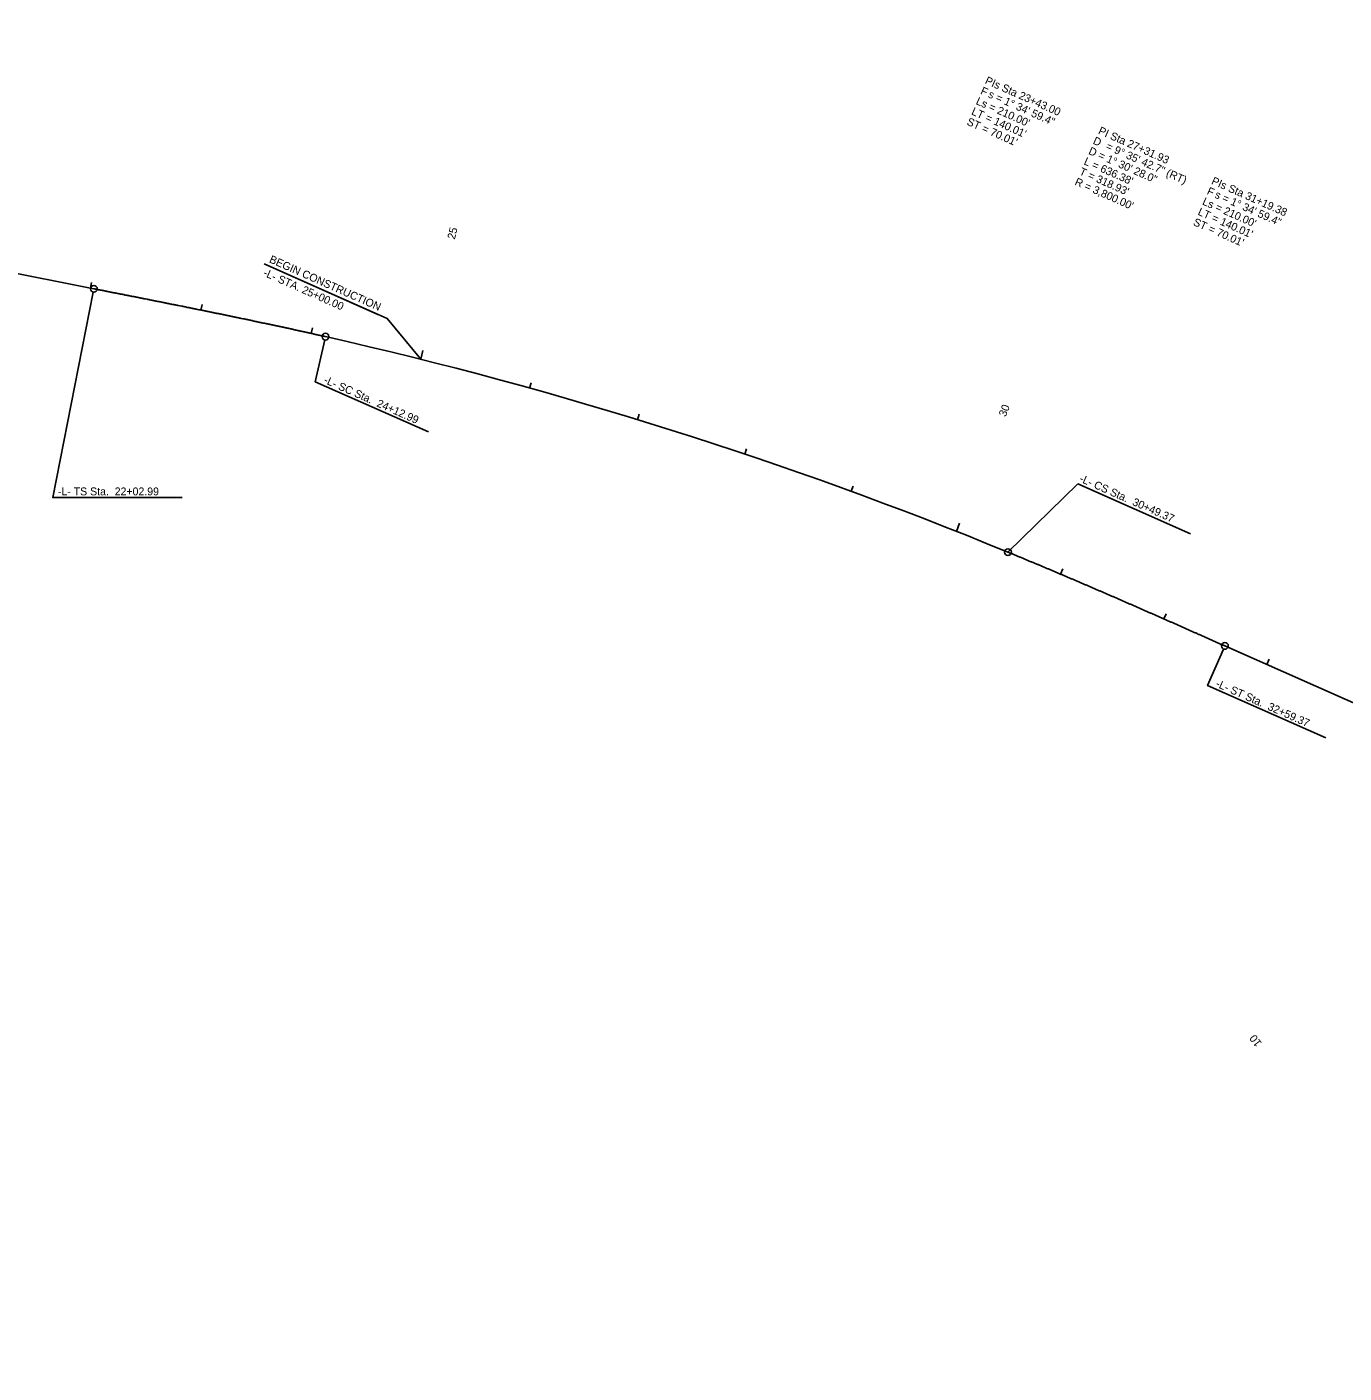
# Model space of a CAD drawing. Extents: x 1636713 to 1642783, y 841520 to 844371.
# Drawn here: x 1637837 to 1639007, y 842626 to 843822 of the extents above; entities that cross this region are included whole.
import ezdxf

# ---------------------------------------------------------------- set-up
doc = ezdxf.new("R2010")
doc.units = 0
for name, color, linetype in [('Prop Horizontal Alignment', 7, 'Continuous'), ('Prop Horizontal Alignment Curve and Spiral Data', 7, 'Continuous'), ('Prop Horizontal Alignment Station Label', 7, 'Continuous'), ('Prop Horizontal Alignment Tick Label', 7, 'Continuous'), ('Prop Horizontal Alignment Tick Large', 7, 'Continuous'), ('Prop Horizontal Alignment Tick Small', 7, 'Continuous')]:
    doc.layers.add(name, color=color, linetype=linetype)

msp = doc.modelspace()

# ---------------------------------------------------------------- linework, layer by layer
at = {"layer": 'Prop Horizontal Alignment'}
for p, q in [((1636716.1, 843822.5), (1637896.4, 843589.8)), ((1638900.9, 843272.5), (1640357.9, 842626.5))]:
    msp.add_line(p, q, dxfattribs=at)
msp.add_arc((1637264.4, 839840.8), 3800, 67.6703, 77.2655, dxfattribs=at)
for points in [[(1637896.4, 843589.8), (1637899.2, 843589.3), (1637902, 843588.7), (1637904.8, 843588.2), (1637907.5, 843587.6), (1637910.3, 843587.1), (1637913.1, 843586.5), (1637915.9, 843586), (1637918.7, 843585.4), (1637921.5, 843584.9), (1637924.2, 843584.3), (1637927, 843583.8), (1637929.8, 843583.2), (1637932.6, 843582.7), (1637935.4, 843582.1), (1637938.2, 843581.6), (1637941, 843581), (1637943.7, 843580.5), (1637946.5, 843579.9), (1637949.3, 843579.4), (1637952.1, 843578.8), (1637954.9, 843578.3), (1637957.7, 843577.7), (1637960.4, 843577.1), (1637963.2, 843576.6), (1637966, 843576), (1637968.8, 843575.5), (1637971.6, 843574.9), (1637974.3, 843574.4), (1637977.1, 843573.8), (1637979.9, 843573.2), (1637982.7, 843572.7), (1637985.5, 843572.1), (1637988.3, 843571.5), (1637991, 843571), (1637993.8, 843570.4), (1637996.6, 843569.8), (1637999.4, 843569.3), (1638002.2, 843568.7), (1638004.9, 843568.1), (1638007.7, 843567.6), (1638010.5, 843567), (1638013.3, 843566.4), (1638016.1, 843565.9), (1638018.8, 843565.3), (1638021.6, 843564.7), (1638024.4, 843564.1), (1638027.2, 843563.5), (1638029.9, 843563), (1638032.7, 843562.4), (1638035.5, 843561.8), (1638038.3, 843561.2), (1638041.1, 843560.6), (1638043.8, 843560), (1638046.6, 843559.4), (1638049.4, 843558.9), (1638052.2, 843558.3), (1638054.9, 843557.7), (1638057.7, 843557.1), (1638060.5, 843556.5), (1638063.3, 843555.9), (1638066, 843555.3), (1638068.8, 843554.7), (1638071.6, 843554.1), (1638074.3, 843553.5), (1638077.1, 843552.9), (1638079.9, 843552.3), (1638082.7, 843551.6), (1638085.4, 843551), (1638088.2, 843550.4), (1638091, 843549.8), (1638093.7, 843549.2), (1638096.5, 843548.6), (1638099.3, 843547.9), (1638102.1, 843547.3)], [(1638900.9, 843272.5), (1638898.3, 843273.6), (1638895.7, 843274.8), (1638893.1, 843275.9), (1638890.5, 843277.1), (1638887.9, 843278.2), (1638885.3, 843279.4), (1638882.7, 843280.5), (1638880.1, 843281.7), (1638877.6, 843282.8), (1638875, 843284), (1638872.4, 843285.1), (1638869.8, 843286.3), (1638867.2, 843287.4), (1638864.6, 843288.6), (1638862, 843289.7), (1638859.4, 843290.9), (1638856.8, 843292), (1638854.2, 843293.2), (1638851.6, 843294.3), (1638849, 843295.5), (1638846.4, 843296.6), (1638843.8, 843297.7), (1638841.2, 843298.9), (1638838.6, 843300), (1638836, 843301.2), (1638833.4, 843302.3), (1638830.8, 843303.5), (1638828.2, 843304.6), (1638825.6, 843305.7), (1638823, 843306.9), (1638820.4, 843308), (1638817.8, 843309.2), (1638815.2, 843310.3), (1638812.6, 843311.4), (1638810, 843312.6), (1638807.4, 843313.7), (1638804.8, 843314.8), (1638802.2, 843316), (1638799.6, 843317.1), (1638797, 843318.2), (1638794.4, 843319.3), (1638791.8, 843320.5), (1638789.2, 843321.6), (1638786.6, 843322.7), (1638784, 843323.9), (1638781.4, 843325), (1638778.8, 843326.1), (1638776.2, 843327.2), (1638773.6, 843328.3), (1638771, 843329.5), (1638768.3, 843330.6), (1638765.7, 843331.7), (1638763.1, 843332.8), (1638760.5, 843333.9), (1638757.9, 843335), (1638755.3, 843336.1), (1638752.7, 843337.2), (1638750.1, 843338.4), (1638747.4, 843339.5), (1638744.8, 843340.6), (1638742.2, 843341.7), (1638739.6, 843342.8), (1638737, 843343.9), (1638734.4, 843345), (1638731.8, 843346.1), (1638729.1, 843347.1), (1638726.5, 843348.2), (1638723.9, 843349.3), (1638721.3, 843350.4), (1638718.7, 843351.5), (1638716, 843352.6), (1638713.4, 843353.7), (1638710.8, 843354.8), (1638708.2, 843355.8)]]:
    msp.add_spline(points, degree=3, dxfattribs=at)
at = {"layer": 'Prop Horizontal Alignment Station Label'}
for p, q in [((1638148.6, 843567.1), (1638047.5, 843612)), ((1638770.3, 843416.4), (1638708.2, 843355.8))]:
    msp.add_line(p, q, dxfattribs=at)
for points in [[(1638047.5, 843612), (1638156.9, 843563.5), (1638186.7, 843527.2)], [(1637895.8, 843586.9), (1637859.8, 843404.3), (1637974.8, 843404.3)], [(1638101.4, 843544.4), (1638093, 843507.3), (1638193.6, 843462.7)], [(1638870.3, 843372), (1638770.3, 843416.4)], [(1638899.7, 843269.7), (1638885.5, 843237.3), (1638990.5, 843190.8)]]:
    msp.add_lwpolyline(points, dxfattribs=at)
for centre in [(1637896.4, 843589.8), (1638102.1, 843547.3), (1638708.2, 843355.8), (1638900.9, 843272.5)]:
    msp.add_circle(centre, 3, dxfattribs=at)
at = {"layer": 'Prop Horizontal Alignment Tick Large'}
for p, q in [((1638186.7, 843527.2), (1638188.6, 843534.9)), ((1638662.4, 843374.3), (1638665.3, 843381.7))]:
    msp.add_line(p, q, dxfattribs=at)
at = {"layer": 'Prop Horizontal Alignment Tick Small'}
for p, q in [((1637893.5, 843590.4), (1637894.4, 843595.3)), ((1637991.5, 843570.9), (1637992.5, 843575.8)), ((1638089.4, 843550.2), (1638090.5, 843555)), ((1638283.4, 843501.6), (1638284.7, 843506.4)), ((1638379.3, 843473.5), (1638380.8, 843478.3)), ((1638474.5, 843442.9), (1638476.1, 843447.7)), ((1638568.9, 843409.9), (1638570.6, 843414.6)), ((1638754.9, 843336.3), (1638756.8, 843340.9)), ((1638846.6, 843296.5), (1638848.6, 843301.1)), ((1638938, 843256), (1638940.1, 843260.6))]:
    msp.add_line(p, q, dxfattribs=at)

# ---------------------------------------------------------------- texts
at = {"layer": 'Prop Horizontal Alignment Curve and Spiral Data'}
for s, p in [('PIs Sta 23+43.00', (1638687.2, 843772.4)), ('F', (1638683.2, 843763.2)), ('s = 1%%d 34\' 59.4"', (1638690, 843760.2)), ("Ls = 210.00'", (1638679.1, 843754.1)), ("ST = 70.01'", (1638671, 843735.8)), ("LT = 140.01'", (1638675.1, 843744.9)), ('PI Sta 27+31.93', (1638787.8, 843727.8)), ('D = 1%%d 30\' 28.0"', (1638779.1, 843709.8)), ('D', (1638783.1, 843718.9)), ('= 9%%d 35\' 42.7" (RT)', (1638794.5, 843714)), ("L = 636.38'", (1638775, 843700.6)), ("T = 318.93'", (1638770.9, 843691.5)), ("R = 3,800.00'", (1638766.9, 843682.4)), ('F', (1638884.3, 843674.1)), ('PIs Sta 31+19.38', (1638888.3, 843683.2)), ("Ls = 210.00'", (1638880.2, 843664.9)), ('s = 1%%d 34\' 59.4"', (1638891.2, 843671)), ("LT = 140.01'", (1638876.2, 843655.8)), ("ST = 70.01'", (1638872.1, 843646.6))]:
    msp.add_text(s, height=7, rotation=336.0871, dxfattribs=at).set_placement(p)
at = {"layer": 'Prop Horizontal Alignment Station Label'}
for s, rotation, p in [('BEGIN CONSTRUCTION', 336.0864, (1638051.5, 843613.5)), ('-L- STA. 25+00.00', 336.0864, (1638046.2, 843601.6)), ('-L- SC Sta.  24+12.99', 336.0871, (1638099.9, 843506.4)), ('-L- CS Sta.  30+49.37', 336.0871, (1638771, 843418.8)), ('-L- ST Sta.  32+59.37', 336.0871, (1638892.1, 843236.6))]:
    msp.add_text(s, height=7, rotation=rotation, dxfattribs=at).set_placement(p)
msp.add_text('-L- TS Sta.  22+02.99', height=7, dxfattribs=at).set_placement((1637864.4, 843406.3))
at = {"layer": 'Prop Horizontal Alignment Tick Label'}
for s, rotation, p in [('25', 75.9536, (1638216.9, 843633.3)), ('30', 68.4147, (1638706.2, 843475.6)), ('10', 127.8269, (1638934, 842919.7))]:
    msp.add_text(s, height=7, rotation=rotation, dxfattribs=at).set_placement(p)

doc.saveas('drawing.dxf')
